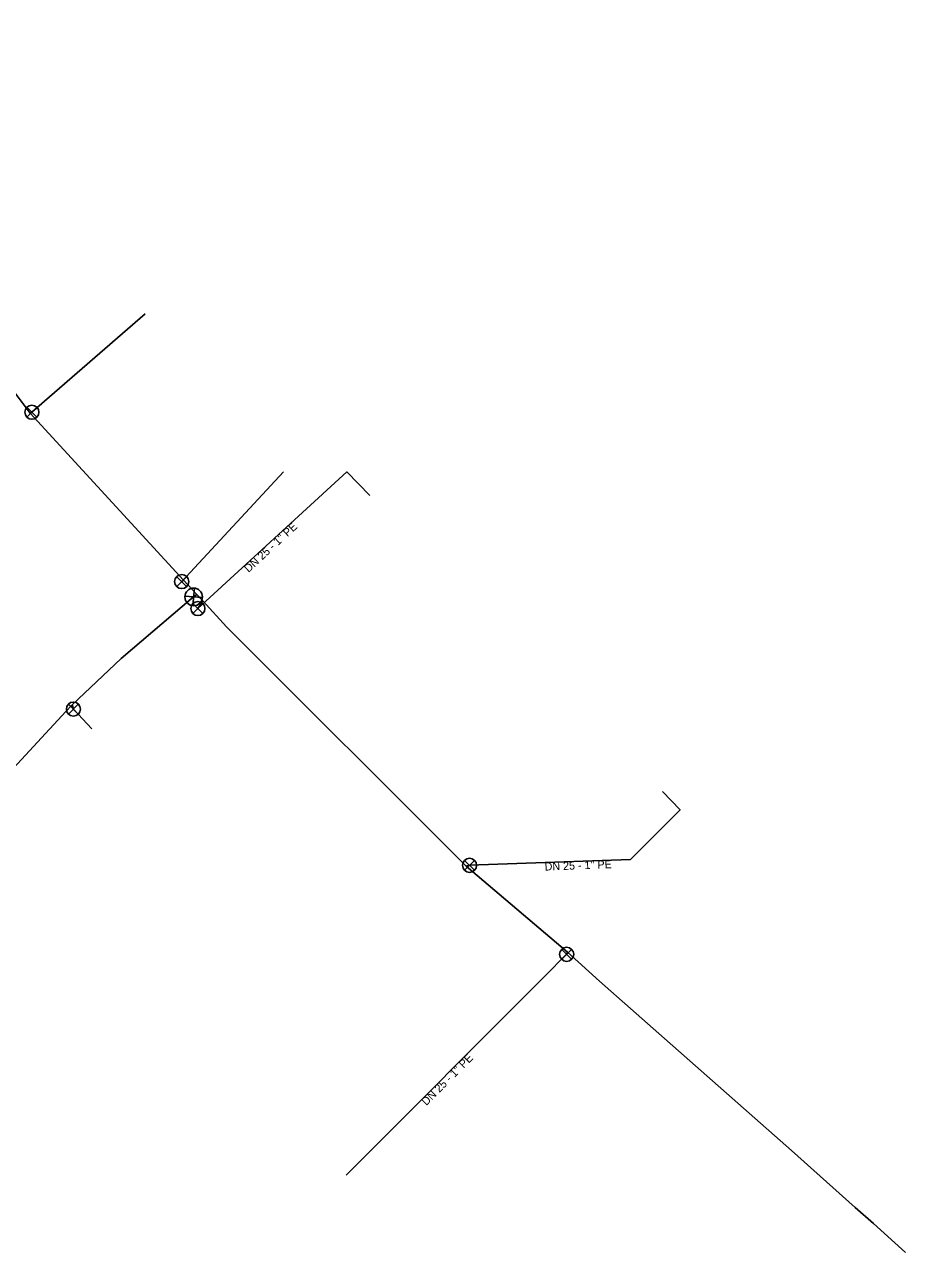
# Model space of a CAD drawing. Extents: x -484784 to -484458, y -1128042 to -1127614.
# Drawn here: x -484508.5 to -484458.4, y -1128041.6 to -1127971.8 of the extents above; entities that cross this region are included whole.
import ezdxf

# ---------------------------------------------------------------- set-up
doc = ezdxf.new("R2010")
doc.units = 0
for name, color, linetype in [('_pripojka_prevzato_z_dokumentace_', 7, 'Continuous'), ('_pripojka_priblizne_', 7, 'Continuous'), ('_voda_smvak_prevzato_z_dokumentace_', 7, 'Continuous'), ('Default', 7, 'Continuous'), ('MoLevel 27', 7, 'Continuous'), ('MoLevel 32', 7, 'Continuous'), ('MoLevel 53', 7, 'Continuous'), ('MoLevel 55', 7, 'Continuous')]:
    doc.layers.add(name, color=color, linetype=linetype)

# ---------------------------------------------------------------- blocks, each defined once
blk = doc.blocks.new('_uzaver_')
at = {"layer": 'Default'}
for p, q in [((-0.000035, -0.000035), (0.000035, 0.000035)), ((0.000035, -0.000035), (-0.000035, 0.000035))]:
    blk.add_line(p, q, dxfattribs=at)
for radius in [0.00005, 0.0000025]:
    blk.add_circle((0, 0), radius, dxfattribs=at)
blk = doc.blocks.new('_uzaver_pripojka_')
at = {"layer": 'Default'}
for p, q in [((-0.000035, -0.000035), (0.000035, 0.000035)), ((0.000035, -0.000035), (-0.000035, 0.000035))]:
    blk.add_line(p, q, dxfattribs=at)
for radius in [0.00005, 0.0000025]:
    blk.add_circle((0, 0), radius, dxfattribs=at)

msp = doc.modelspace()

# ---------------------------------------------------------------- linework, layer by layer
at = {"layer": '_pripojka_prevzato_z_dokumentace_'}
msp.add_line((-484478.873, -1128025.934), (-484490.176, -1128037.244), dxfattribs=at)
for points in [[(-484508.14, -1127993.922), (-484508.04, -1127993.87), (-484501.598, -1127988.28)], [(-484506.104, -1128010.894), (-484509.795, -1128014.863), (-484514.633, -1128019.619), (-484515.667, -1128020.706), (-484524.251, -1128035.815), (-484527.56, -1128041.639)], [(-484505.744, -1128010.507), (-484505.68, -1128010.75), (-484504.632, -1128011.868)], [(-484477.581, -1128024.567), (-484477.63, -1128024.69), (-484478.873, -1128025.934)]]:
    msp.add_lwpolyline(points, dxfattribs=at)
at = {"layer": '_pripojka_priblizne_'}
for points in [[(-484499.415, -1128003.417), (-484499.52, -1128003.5), (-484493.73, -1127997.25)], [(-484498.327, -1128004.595), (-484498.6, -1128005.03), (-484490.128, -1127997.263), (-484488.817, -1127998.598)], [(-484474.004, -1128019.301), (-484471.176, -1128016.472), (-484472.186, -1128015.434)], [(-484483.342, -1128019.687), (-484483.15, -1128019.63), (-484474.004, -1128019.301)]]:
    msp.add_lwpolyline(points, dxfattribs=at)
at = {"layer": '_voda_smvak_prevzato_z_dokumentace_'}
msp.add_line((-484498.654, -1128004.24), (-484498.84, -1128004.37), dxfattribs=at)
for points in [[(-484526.49, -1127971.83), (-484520.118, -1127979.356), (-484519.464, -1127980.256), (-484515.636, -1127984.875), (-484513.731, -1127987.283), (-484513.597, -1127987.411), (-484513.325, -1127987.673), (-484511.629, -1127989.368), (-484511.163, -1127989.903), (-484508.14, -1127993.922), (-484499.415, -1128003.417), (-484498.654, -1128004.24)], [(-484498.84, -1128004.37), (-484502.967, -1128007.863), (-484505.744, -1128010.507), (-484506.104, -1128010.894)], [(-484458.364, -1128041.639), (-484460.172, -1128040.002), (-484461.219, -1128039.08), (-484464.847, -1128035.836), (-484475.755, -1128026.217), (-484477.581, -1128024.567), (-484483.342, -1128019.687), (-484496.968, -1128006.077), (-484498.327, -1128004.595), (-484498.654, -1128004.24)]]:
    msp.add_lwpolyline(points, dxfattribs=at)

# ---------------------------------------------------------------- block references
at = {"layer": 'MoLevel 27', "xscale": 10000, "yscale": 10000, "rotation": -139.74494292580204}
msp.add_blockref('_uzaver_', (-484498.84, -1128004.37), dxfattribs=at)
at = {"layer": 'MoLevel 53', "xscale": 7999.999999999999, "yscale": 7999.999999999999}
for p in [(-484508.04, -1127993.87), (-484499.52, -1128003.5), (-484498.6, -1128005.03), (-484505.68, -1128010.75), (-484483.15, -1128019.63), (-484477.63, -1128024.69)]:
    msp.add_blockref('_uzaver_pripojka_', p, dxfattribs=at)

# ---------------------------------------------------------------- texts
at = {"layer": 'MoLevel 32'}
for rotation, p in [(42.51412, (-484495.72, -1128003.007)), (2.06016, (-484478.872, -1128019.931))]:
    msp.add_text("DN 25 - 1'' PE", height=0.455, rotation=rotation, dxfattribs=at).set_placement(p)
at = {"layer": 'MoLevel 55'}
msp.add_text("DN 25 - 1'' PE", height=0.455, rotation=45.01826, dxfattribs=at).set_placement((-484485.61, -1128033.318))

doc.saveas('drawing.dxf')
